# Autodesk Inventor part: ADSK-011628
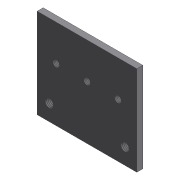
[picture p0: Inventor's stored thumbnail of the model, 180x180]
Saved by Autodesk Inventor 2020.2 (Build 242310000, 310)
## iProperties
Created: 2000-02
Part Number: ADSK-011628
Material: Pearson HRS
Document SubType Name: Modeling
Designer: sspink
Density: 7.83 g/cm^3
Appearance: Métal - Acier
Mass: 412.752 g
Surface Area: 205.43 cm^2
Volume: 52.7142 cm^3
Control State: 0
Checked Out: False
Master: False
Shininess: 0.0
Length Units: 11269
Angle Units: 11279
Time Units: 11290
Mass Units: 11283
Length Display Precision: 3
Angle Display Precision: 2
Compacted: True
Cutlength: 4
Material Desc: FLAT,HRS,0.25 X 3.50
Material_Number: A084334
Dimensions: 90x6x100 mm
Mass: 0,413 kg
VLT_Material: Pearson HRS
Density: 0.0
Volumn: 0.0
Area: 0.0
PropertySet Name: Model Information
Author: sspink
Revision Number: -
Title: ADSK-011628
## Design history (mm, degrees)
sketch "Sketch3"
  geometry: L1 (-31, 9)-(31, 9); L2 (-50, 45)-(50, 45) reference; 3 further points
  constraints: 2 end point, 2 midpoint, 1 coincident, 1 horizontal, 1 vertical alignment
  dimensions: "d26" = 62 distance of L1.start L1.end; "d27" = 36 distance between parallel lines of L1 L2
node "Hole2" dims "d10" = 6.647, "d11" = 9.525, "d12" = 6.35, "d13" = 60 deg, "d14" = 19.05, "d15" = 118 deg, "d25" = 16
node "Solide1"
  node "Extrusion1" dims "d2" = 6, "d3" = 0
  node "Hole1" dims "d4" = 8.376, "d5" = 9.525, "d6" = 6.35, "d7" = 60 deg, "d8" = 27.3, "d9" = 118 deg, "d24" = 20
sketch "Sketch1"
  geometry: L1 (-50, -45)-(50, -45); L2 (50, -45)-(50, 45); L3 (50, 45)-(-50, 45); L4 (-50, 45)-(-50, -45); 3 further points
  constraints: 8 end point, 2 midpoint, 2 parallel, 1 horizontal, 1 horizontal alignment, 1 perpendicular, 1 vertical alignment
  dimensions: "d0" = 100 distance between parallel lines of L2 L4; "d1" = 90 distance between parallel lines of L3 L1
sketch "Sketch2"
  geometry: L1 (-38, -29)-(38, -29); L2 (50, -45)-(-50, -45) reference; 2 further points
  constraints: 2 end point, 2 midpoint, 1 horizontal, 1 vertical alignment
  dimensions: "d22" = 16 distance between parallel lines of L2 L1; "d23" = 76 distance of L1.start L1.end
node "Corps solides"
node "Corps surfaciques"
